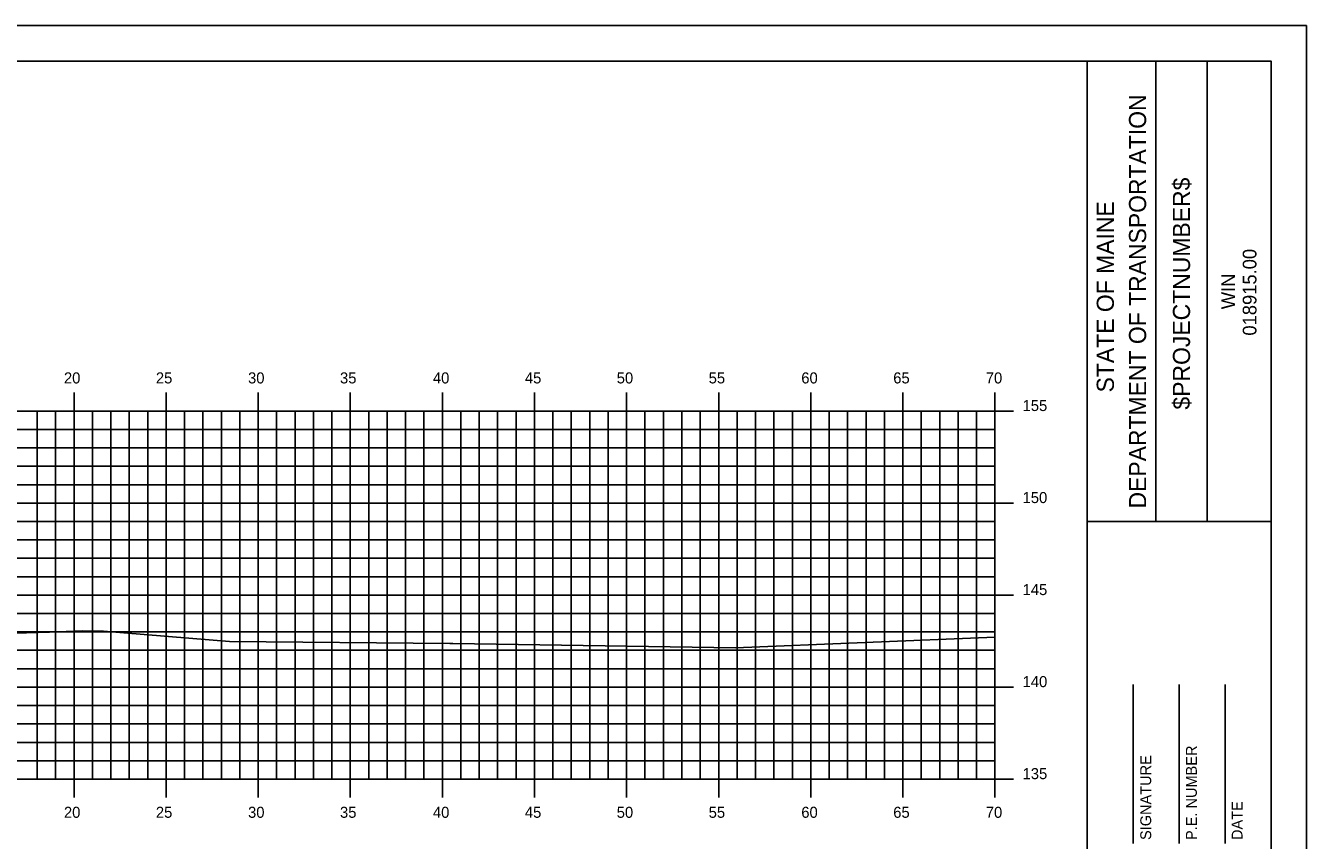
# Model space of a CAD drawing. Extents: x 850973 to 851145, y 365876 to 365986.
# Drawn here: x 851073.8 to 851143.3, y 365941.5 to 365985.8 of the extents above; entities that cross this region are included whole.
import ezdxf

# ---------------------------------------------------------------- set-up
doc = ezdxf.new("R2010")
doc.units = 0
for name, color, linetype in [('BORDER', 7, 'Continuous'), ('H_V ANNOTATION', 7, 'Continuous'), ('MAJOR', 7, 'Continuous'), ('MINOR', 7, 'Continuous'), ('PLOT BOUNDARY', 7, 'Continuous'), ('S_Roadway_Centerline', 7, 'Continuous')]:
    doc.layers.add(name, color=color, linetype=linetype)

msp = doc.modelspace()

# ---------------------------------------------------------------- linework, layer by layer
at = {"layer": 'BORDER'}
for p, q in [((851131.386, 365878.833), (851131.386, 365983.833)), ((851135.114, 365958.83), (851135.114, 365983.83)), ((851137.909, 365958.83), (851137.909, 365983.83)), ((851131.386, 365958.827), (851141.386, 365958.827)), ((851133.886, 365941.336), (851133.886, 365949.984)), ((851136.386, 365941.336), (851136.386, 365949.984)), ((851138.886, 365941.336), (851138.886, 365949.984))]:
    msp.add_line(p, q, dxfattribs=at)
msp.add_lwpolyline([(850981.386, 365878.833), (851141.386, 365878.833), (851141.386, 365983.833), (850981.386, 365983.833)], close=True, dxfattribs=at)
at = {"layer": 'MAJOR'}
for p, q in [((851076.385, 365965.835), (851076.385, 365964.833)), ((851081.385, 365965.835), (851081.385, 365964.833)), ((851086.385, 365965.835), (851086.385, 365964.833)), ((851091.385, 365965.835), (851091.385, 365964.833)), ((851096.385, 365965.835), (851096.385, 365964.833)), ((851101.385, 365965.835), (851101.385, 365964.833)), ((851106.385, 365965.835), (851106.385, 365964.833)), ((851111.385, 365965.835), (851111.385, 365964.833)), ((851116.385, 365965.835), (851116.385, 365964.833)), ((851121.385, 365965.835), (851121.385, 365964.833)), ((851126.385, 365965.835), (851126.385, 365964.833)), ((850986.385, 365964.833), (851126.385, 365964.833)), ((850986.385, 365964.833), (851126.385, 365964.833)), ((851076.385, 365944.833), (851076.385, 365964.833)), ((851081.385, 365944.833), (851081.385, 365964.833)), ((851086.385, 365944.833), (851086.385, 365964.833)), ((851091.385, 365944.833), (851091.385, 365964.833)), ((851096.385, 365944.833), (851096.385, 365964.833)), ((851101.385, 365944.833), (851101.385, 365964.833)), ((851106.385, 365944.833), (851106.385, 365964.833)), ((851111.385, 365944.833), (851111.385, 365964.833)), ((851116.385, 365944.833), (851116.385, 365964.833)), ((851121.385, 365944.833), (851121.385, 365964.833)), ((851127.387, 365964.833), (851125.383, 365964.833)), ((851126.385, 365944.833), (851126.385, 365964.833)), ((851126.385, 365944.833), (851126.385, 365964.833)), ((850986.385, 365959.833), (851126.385, 365959.833)), ((851127.387, 365959.833), (851125.383, 365959.833)), ((850986.385, 365954.833), (851126.385, 365954.833)), ((851127.387, 365954.833), (851125.383, 365954.833)), ((850986.385, 365949.833), (851126.385, 365949.833)), ((851127.387, 365949.833), (851125.383, 365949.833)), ((850986.385, 365944.833), (851126.385, 365944.833)), ((850986.385, 365944.833), (851126.385, 365944.833)), ((851076.385, 365943.831), (851076.385, 365944.833)), ((851081.385, 365943.831), (851081.385, 365944.833)), ((851086.385, 365943.831), (851086.385, 365944.833)), ((851091.385, 365943.831), (851091.385, 365944.833)), ((851096.385, 365943.831), (851096.385, 365944.833)), ((851101.385, 365943.831), (851101.385, 365944.833)), ((851106.385, 365943.831), (851106.385, 365944.833)), ((851111.385, 365943.831), (851111.385, 365944.833)), ((851116.385, 365943.831), (851116.385, 365944.833)), ((851121.385, 365943.831), (851121.385, 365944.833)), ((851127.387, 365944.833), (851125.383, 365944.833)), ((851126.385, 365943.831), (851126.385, 365944.833))]:
    msp.add_line(p, q, dxfattribs=at)
at = {"layer": 'MINOR'}
for p, q in [((851074.385, 365944.833), (851074.385, 365964.833)), ((851075.385, 365944.833), (851075.385, 365964.833)), ((851077.385, 365944.833), (851077.385, 365964.833)), ((851078.385, 365944.833), (851078.385, 365964.833)), ((851079.385, 365944.833), (851079.385, 365964.833)), ((851080.385, 365944.833), (851080.385, 365964.833)), ((851082.385, 365944.833), (851082.385, 365964.833)), ((851083.385, 365944.833), (851083.385, 365964.833)), ((851084.385, 365944.833), (851084.385, 365964.833)), ((851085.385, 365944.833), (851085.385, 365964.833)), ((851087.385, 365944.833), (851087.385, 365964.833)), ((851088.385, 365944.833), (851088.385, 365964.833)), ((851089.385, 365944.833), (851089.385, 365964.833)), ((851090.385, 365944.833), (851090.385, 365964.833)), ((851092.385, 365944.833), (851092.385, 365964.833)), ((851093.385, 365944.833), (851093.385, 365964.833)), ((851094.385, 365944.833), (851094.385, 365964.833)), ((851095.385, 365944.833), (851095.385, 365964.833)), ((851097.385, 365944.833), (851097.385, 365964.833)), ((851098.385, 365944.833), (851098.385, 365964.833)), ((851099.385, 365944.833), (851099.385, 365964.833)), ((851100.385, 365944.833), (851100.385, 365964.833)), ((851102.385, 365944.833), (851102.385, 365964.833)), ((851103.385, 365944.833), (851103.385, 365964.833)), ((851104.385, 365944.833), (851104.385, 365964.833)), ((851105.385, 365944.833), (851105.385, 365964.833)), ((851107.385, 365944.833), (851107.385, 365964.833)), ((851108.385, 365944.833), (851108.385, 365964.833)), ((851109.385, 365944.833), (851109.385, 365964.833)), ((851110.385, 365944.833), (851110.385, 365964.833)), ((851112.385, 365944.833), (851112.385, 365964.833)), ((851113.385, 365944.833), (851113.385, 365964.833)), ((851114.385, 365944.833), (851114.385, 365964.833)), ((851115.385, 365944.833), (851115.385, 365964.833)), ((851117.385, 365944.833), (851117.385, 365964.833)), ((851118.385, 365944.833), (851118.385, 365964.833)), ((851119.385, 365944.833), (851119.385, 365964.833)), ((851120.385, 365944.833), (851120.385, 365964.833)), ((851122.385, 365944.833), (851122.385, 365964.833)), ((851123.385, 365944.833), (851123.385, 365964.833)), ((851124.385, 365944.833), (851124.385, 365964.833)), ((851125.385, 365944.833), (851125.385, 365964.833)), ((850986.385, 365963.833), (851126.385, 365963.833)), ((851126.385, 365963.833), (851125.383, 365963.833)), ((850986.385, 365962.833), (851126.385, 365962.833)), ((851126.385, 365962.833), (851125.383, 365962.833)), ((850986.385, 365961.833), (851126.385, 365961.833)), ((851126.385, 365961.833), (851125.383, 365961.833)), ((850986.385, 365960.833), (851126.385, 365960.833)), ((851126.385, 365960.833), (851125.383, 365960.833)), ((850986.385, 365958.833), (851126.385, 365958.833)), ((851126.385, 365958.833), (851125.383, 365958.833)), ((850986.385, 365957.833), (851126.385, 365957.833)), ((851126.385, 365957.833), (851125.383, 365957.833)), ((850986.385, 365956.833), (851126.385, 365956.833)), ((851126.385, 365956.833), (851125.383, 365956.833)), ((850986.385, 365955.833), (851126.385, 365955.833)), ((851126.385, 365955.833), (851125.383, 365955.833)), ((850986.385, 365953.833), (851126.385, 365953.833)), ((851126.385, 365953.833), (851125.383, 365953.833)), ((850986.385, 365952.833), (851126.385, 365952.833)), ((851126.385, 365952.833), (851125.383, 365952.833)), ((850986.385, 365951.833), (851126.385, 365951.833)), ((851126.385, 365951.833), (851125.383, 365951.833)), ((850986.385, 365950.833), (851126.385, 365950.833)), ((851126.385, 365950.833), (851125.383, 365950.833)), ((850986.385, 365948.833), (851126.385, 365948.833)), ((851126.385, 365948.833), (851125.383, 365948.833)), ((850986.385, 365947.833), (851126.385, 365947.833)), ((851126.385, 365947.833), (851125.383, 365947.833)), ((850986.385, 365946.833), (851126.385, 365946.833)), ((851126.385, 365946.833), (851125.383, 365946.833)), ((850986.385, 365945.833), (851126.385, 365945.833)), ((851126.385, 365945.833), (851125.383, 365945.833))]:
    msp.add_line(p, q, dxfattribs=at)
at = {"layer": 'PLOT BOUNDARY'}
msp.add_lwpolyline([(850973.292, 365875.774), (851143.292, 365875.774), (851143.292, 365985.774), (850973.292, 365985.774)], close=True, dxfattribs=at)
at = {"layer": 'S_Roadway_Centerline'}
msp.add_lwpolyline([(851073.187, 365952.773), (851075.061, 365952.821), (851076.869, 365952.891), (851077.993, 365952.869), (851084.829, 365952.313), (851096.787, 365952.202), (851096.807, 365952.201), (851096.822, 365952.201), (851096.835, 365952.202), (851096.96, 365952.199), (851112.299, 365951.972), (851126.385, 365952.552)], dxfattribs=at)

# ---------------------------------------------------------------- texts
at = {"layer": 'BORDER'}
for s, height, p in [('DEPARTMENT OF TRANSPORTATION', 0.93176, (851134.592, 365959.539)), ('$PROJECTNUMBER$', 0.93176, (851136.977, 365964.912)), ('STATE OF MAINE', 0.93176, (851132.841, 365965.845)), ('018915.00', 0.7453, (851140.581, 365968.931)), ('WIN', 0.7453, (851139.422, 365970.363)), ('P.E. NUMBER', 0.59055, (851137.346, 365941.528)), ('SIGNATURE', 0.5906, (851134.866, 365941.528)), ('DATE', 0.5906, (851139.827, 365941.528))]:
    msp.add_text(s, height=height, rotation=90, dxfattribs=at).set_placement(p)
at = {"layer": 'H_V ANNOTATION'}
for s, p in [('20', (851075.839, 365966.333)), ('25', (851080.831, 365966.333)), ('30', (851085.834, 365966.333)), ('35', (851090.826, 365966.333)), ('40', (851095.871, 365966.333)), ('45', (851100.863, 365966.333)), ('50', (851105.85, 365966.333)), ('55', (851110.842, 365966.333)), ('60', (851115.871, 365966.333)), ('65', (851120.863, 365966.333)), ('70', (851125.887, 365966.333)), ('155', (851127.885, 365964.833)), ('150', (851127.885, 365959.833)), ('145', (851127.885, 365954.833)), ('140', (851127.885, 365949.833)), ('135', (851127.885, 365944.833)), ('20', (851075.839, 365942.733)), ('25', (851080.831, 365942.733)), ('30', (851085.834, 365942.733)), ('35', (851090.826, 365942.733)), ('40', (851095.871, 365942.733)), ('45', (851100.863, 365942.733)), ('50', (851105.85, 365942.733)), ('55', (851110.842, 365942.733)), ('60', (851115.871, 365942.733)), ('65', (851120.863, 365942.733)), ('70', (851125.887, 365942.733))]:
    msp.add_text(s, height=0.6, dxfattribs=at).set_placement(p)

doc.saveas('drawing.dxf')
